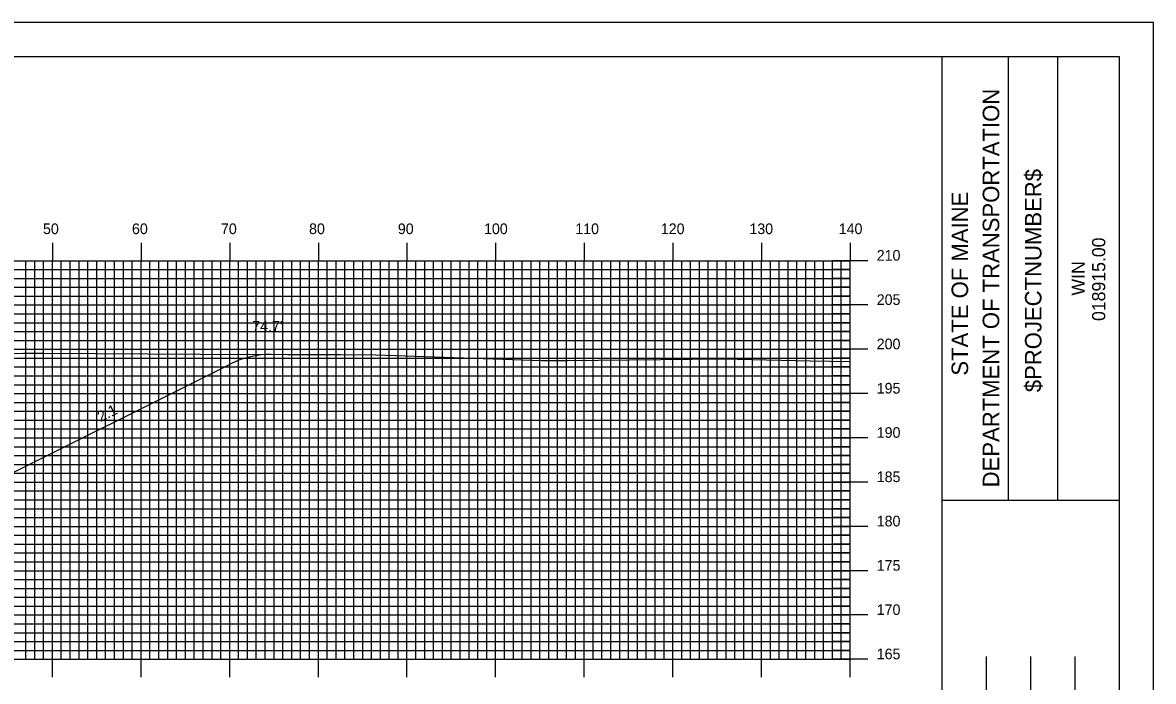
# Model space of a CAD drawing. Extents: x 1796027 to 1796370, y 442591 to 442811.
# Drawn here: x 1796239 to 1796366.6, y 442736.2 to 442810.5 of the extents above; entities that cross this region are included whole.
import ezdxf

# ---------------------------------------------------------------- set-up
doc = ezdxf.new("R2010")
doc.units = 0
for name, color, linetype in [('ANNOTATION', 7, 'Continuous'), ('BORDER', 7, 'Continuous'), ('D_Roadway_SlopeLines', 7, 'Continuous'), ('D_Text_Standard', 7, 'Continuous'), ('H_V ANNOTATION', 7, 'Continuous'), ('MAJOR', 7, 'Continuous'), ('MINOR', 7, 'Continuous'), ('PLOT BOUNDARY', 7, 'Continuous'), ('S_Roadway_Centerline', 7, 'Continuous')]:
    doc.layers.add(name, color=color, linetype=linetype)

msp = doc.modelspace()

# ---------------------------------------------------------------- linework, layer by layer
at = {"layer": 'ANNOTATION'}
msp.add_arc((1796267, 442763.09), 10, 89.662, 116.5651, dxfattribs=at)
msp.add_arc((1796267, 442763.09), 10, 89.662, 116.5651, dxfattribs=at)
at = {"layer": 'BORDER'}
for p, q in [((1796342.79, 442596.67), (1796342.79, 442806.67)), ((1796350.25, 442756.66), (1796350.25, 442806.66)), ((1796355.84, 442756.66), (1796355.84, 442806.66)), ((1796342.79, 442756.65), (1796362.79, 442756.65)), ((1796347.79, 442721.67), (1796347.79, 442738.97)), ((1796352.79, 442721.67), (1796352.79, 442738.97)), ((1796357.79, 442721.67), (1796357.79, 442738.97))]:
    msp.add_line(p, q, dxfattribs=at)
msp.add_lwpolyline([(1796042.79, 442596.67), (1796362.79, 442596.67), (1796362.79, 442806.67), (1796042.79, 442806.67)], close=True, dxfattribs=at)
at = {"layer": 'D_Roadway_SlopeLines'}
msp.add_lwpolyline([(1796228.99, 442758.27), (1796234.99, 442758.27), (1796262.53, 442772.04)], dxfattribs=at)
at = {"layer": 'MAJOR'}
for p, q in [((1796242.39, 442785.67), (1796242.39, 442783.67)), ((1796252.39, 442785.67), (1796252.39, 442783.67)), ((1796262.39, 442785.67), (1796262.39, 442783.67)), ((1796272.39, 442785.67), (1796272.39, 442783.67)), ((1796282.39, 442785.67), (1796282.39, 442783.67)), ((1796292.39, 442785.67), (1796292.39, 442783.67)), ((1796302.39, 442785.67), (1796302.39, 442783.67)), ((1796312.39, 442785.67), (1796312.39, 442783.67)), ((1796322.39, 442785.67), (1796322.39, 442783.67)), ((1796332.39, 442785.67), (1796332.39, 442783.67)), ((1796052.39, 442783.67), (1796332.39, 442783.67)), ((1796052.39, 442783.67), (1796332.39, 442783.67)), ((1796242.39, 442738.67), (1796242.39, 442783.67)), ((1796252.39, 442738.67), (1796252.39, 442783.67)), ((1796262.39, 442738.67), (1796262.39, 442783.67)), ((1796272.39, 442738.67), (1796272.39, 442783.67)), ((1796282.39, 442738.67), (1796282.39, 442783.67)), ((1796292.39, 442738.67), (1796292.39, 442783.67)), ((1796302.39, 442738.67), (1796302.39, 442783.67)), ((1796312.39, 442738.67), (1796312.39, 442783.67)), ((1796322.39, 442738.67), (1796322.39, 442783.67)), ((1796334.4, 442783.67), (1796330.39, 442783.67)), ((1796332.39, 442738.67), (1796332.39, 442783.67)), ((1796332.39, 442738.67), (1796332.39, 442783.67)), ((1796052.39, 442778.67), (1796332.39, 442778.67)), ((1796334.4, 442778.67), (1796330.39, 442778.67)), ((1796052.39, 442773.67), (1796332.39, 442773.67)), ((1796334.4, 442773.67), (1796330.39, 442773.67)), ((1796052.39, 442768.67), (1796332.39, 442768.67)), ((1796334.4, 442768.67), (1796330.39, 442768.67)), ((1796052.39, 442763.67), (1796332.39, 442763.67)), ((1796334.4, 442763.67), (1796330.39, 442763.67)), ((1796052.39, 442758.67), (1796332.39, 442758.67)), ((1796334.4, 442758.67), (1796330.39, 442758.67)), ((1796052.39, 442753.67), (1796332.39, 442753.67)), ((1796334.4, 442753.67), (1796330.39, 442753.67)), ((1796052.39, 442748.67), (1796332.39, 442748.67)), ((1796334.4, 442748.67), (1796330.39, 442748.67)), ((1796052.39, 442743.67), (1796332.39, 442743.67)), ((1796334.4, 442743.67), (1796330.39, 442743.67)), ((1796052.39, 442738.67), (1796332.39, 442738.67)), ((1796052.39, 442738.67), (1796332.39, 442738.67)), ((1796242.39, 442736.66), (1796242.39, 442738.67)), ((1796252.39, 442736.66), (1796252.39, 442738.67)), ((1796262.39, 442736.66), (1796262.39, 442738.67)), ((1796272.39, 442736.66), (1796272.39, 442738.67)), ((1796282.39, 442736.66), (1796282.39, 442738.67)), ((1796292.39, 442736.66), (1796292.39, 442738.67)), ((1796302.39, 442736.66), (1796302.39, 442738.67)), ((1796312.39, 442736.66), (1796312.39, 442738.67)), ((1796322.39, 442736.66), (1796322.39, 442738.67)), ((1796334.4, 442738.67), (1796330.39, 442738.67)), ((1796332.39, 442736.66), (1796332.39, 442738.67))]:
    msp.add_line(p, q, dxfattribs=at)
at = {"layer": 'MINOR'}
for p, q in [((1796239.39, 442738.67), (1796239.39, 442783.67)), ((1796240.39, 442738.67), (1796240.39, 442783.67)), ((1796241.39, 442738.67), (1796241.39, 442783.67)), ((1796243.39, 442738.67), (1796243.39, 442783.67)), ((1796244.39, 442738.67), (1796244.39, 442783.67)), ((1796245.39, 442738.67), (1796245.39, 442783.67)), ((1796246.39, 442738.67), (1796246.39, 442783.67)), ((1796247.39, 442738.67), (1796247.39, 442783.67)), ((1796248.39, 442738.67), (1796248.39, 442783.67)), ((1796249.39, 442738.67), (1796249.39, 442783.67)), ((1796250.39, 442738.67), (1796250.39, 442783.67)), ((1796251.39, 442738.67), (1796251.39, 442783.67)), ((1796253.39, 442738.67), (1796253.39, 442783.67)), ((1796254.39, 442738.67), (1796254.39, 442783.67)), ((1796255.39, 442738.67), (1796255.39, 442783.67)), ((1796256.39, 442738.67), (1796256.39, 442783.67)), ((1796257.39, 442738.67), (1796257.39, 442783.67)), ((1796258.39, 442738.67), (1796258.39, 442783.67)), ((1796259.39, 442738.67), (1796259.39, 442783.67)), ((1796260.39, 442738.67), (1796260.39, 442783.67)), ((1796261.39, 442738.67), (1796261.39, 442783.67)), ((1796263.39, 442738.67), (1796263.39, 442783.67)), ((1796264.39, 442738.67), (1796264.39, 442783.67)), ((1796265.39, 442738.67), (1796265.39, 442783.67)), ((1796266.39, 442738.67), (1796266.39, 442783.67)), ((1796267.39, 442738.67), (1796267.39, 442783.67)), ((1796268.39, 442738.67), (1796268.39, 442783.67)), ((1796269.39, 442738.67), (1796269.39, 442783.67)), ((1796270.39, 442738.67), (1796270.39, 442783.67)), ((1796271.39, 442738.67), (1796271.39, 442783.67)), ((1796273.39, 442738.67), (1796273.39, 442783.67)), ((1796274.39, 442738.67), (1796274.39, 442783.67)), ((1796275.39, 442738.67), (1796275.39, 442783.67)), ((1796276.39, 442738.67), (1796276.39, 442783.67)), ((1796277.39, 442738.67), (1796277.39, 442783.67)), ((1796278.39, 442738.67), (1796278.39, 442783.67)), ((1796279.39, 442738.67), (1796279.39, 442783.67)), ((1796280.39, 442738.67), (1796280.39, 442783.67)), ((1796281.39, 442738.67), (1796281.39, 442783.67)), ((1796283.39, 442738.67), (1796283.39, 442783.67)), ((1796284.39, 442738.67), (1796284.39, 442783.67)), ((1796285.39, 442738.67), (1796285.39, 442783.67)), ((1796286.39, 442738.67), (1796286.39, 442783.67)), ((1796287.39, 442738.67), (1796287.39, 442783.67)), ((1796288.39, 442738.67), (1796288.39, 442783.67)), ((1796289.39, 442738.67), (1796289.39, 442783.67)), ((1796290.39, 442738.67), (1796290.39, 442783.67)), ((1796291.39, 442738.67), (1796291.39, 442783.67)), ((1796293.39, 442738.67), (1796293.39, 442783.67)), ((1796294.39, 442738.67), (1796294.39, 442783.67)), ((1796295.39, 442738.67), (1796295.39, 442783.67)), ((1796296.39, 442738.67), (1796296.39, 442783.67)), ((1796297.39, 442738.67), (1796297.39, 442783.67)), ((1796298.39, 442738.67), (1796298.39, 442783.67)), ((1796299.39, 442738.67), (1796299.39, 442783.67)), ((1796300.39, 442738.67), (1796300.39, 442783.67)), ((1796301.39, 442738.67), (1796301.39, 442783.67)), ((1796303.39, 442738.67), (1796303.39, 442783.67)), ((1796304.39, 442738.67), (1796304.39, 442783.67)), ((1796305.39, 442738.67), (1796305.39, 442783.67)), ((1796306.39, 442738.67), (1796306.39, 442783.67)), ((1796307.39, 442738.67), (1796307.39, 442783.67)), ((1796308.39, 442738.67), (1796308.39, 442783.67)), ((1796309.39, 442738.67), (1796309.39, 442783.67)), ((1796310.39, 442738.67), (1796310.39, 442783.67)), ((1796311.39, 442738.67), (1796311.39, 442783.67)), ((1796313.39, 442738.67), (1796313.39, 442783.67)), ((1796314.39, 442738.67), (1796314.39, 442783.67)), ((1796315.39, 442738.67), (1796315.39, 442783.67)), ((1796316.39, 442738.67), (1796316.39, 442783.67)), ((1796317.39, 442738.67), (1796317.39, 442783.67)), ((1796318.39, 442738.67), (1796318.39, 442783.67)), ((1796319.39, 442738.67), (1796319.39, 442783.67)), ((1796320.39, 442738.67), (1796320.39, 442783.67)), ((1796321.39, 442738.67), (1796321.39, 442783.67)), ((1796323.39, 442738.67), (1796323.39, 442783.67)), ((1796324.39, 442738.67), (1796324.39, 442783.67)), ((1796325.39, 442738.67), (1796325.39, 442783.67)), ((1796326.39, 442738.67), (1796326.39, 442783.67)), ((1796327.39, 442738.67), (1796327.39, 442783.67)), ((1796328.39, 442738.67), (1796328.39, 442783.67)), ((1796329.39, 442738.67), (1796329.39, 442783.67)), ((1796330.39, 442738.67), (1796330.39, 442783.67)), ((1796331.39, 442738.67), (1796331.39, 442783.67)), ((1796052.39, 442782.67), (1796332.39, 442782.67)), ((1796332.39, 442782.67), (1796330.39, 442782.67)), ((1796052.39, 442781.67), (1796332.39, 442781.67)), ((1796332.39, 442781.67), (1796330.39, 442781.67)), ((1796052.39, 442780.67), (1796332.39, 442780.67)), ((1796052.39, 442779.67), (1796332.39, 442779.67)), ((1796332.39, 442780.67), (1796330.39, 442780.67)), ((1796332.39, 442779.67), (1796330.39, 442779.67)), ((1796052.39, 442777.67), (1796332.39, 442777.67)), ((1796332.39, 442777.67), (1796330.39, 442777.67)), ((1796052.39, 442776.67), (1796332.39, 442776.67)), ((1796052.39, 442775.67), (1796332.39, 442775.67)), ((1796332.39, 442776.67), (1796330.39, 442776.67)), ((1796332.39, 442775.67), (1796330.39, 442775.67)), ((1796052.39, 442774.67), (1796332.39, 442774.67)), ((1796332.39, 442774.67), (1796330.39, 442774.67)), ((1796052.39, 442772.67), (1796332.39, 442772.67)), ((1796332.39, 442772.67), (1796330.39, 442772.67)), ((1796052.39, 442771.67), (1796332.39, 442771.67)), ((1796052.39, 442770.67), (1796332.39, 442770.67)), ((1796332.39, 442771.67), (1796330.39, 442771.67)), ((1796332.39, 442770.67), (1796330.39, 442770.67)), ((1796052.39, 442769.67), (1796332.39, 442769.67)), ((1796332.39, 442769.67), (1796330.39, 442769.67)), ((1796052.39, 442767.67), (1796332.39, 442767.67)), ((1796052.39, 442766.67), (1796332.39, 442766.67)), ((1796332.39, 442767.67), (1796330.39, 442767.67)), ((1796332.39, 442766.67), (1796330.39, 442766.67)), ((1796052.39, 442765.67), (1796332.39, 442765.67)), ((1796332.39, 442765.67), (1796330.39, 442765.67)), ((1796052.39, 442764.67), (1796332.39, 442764.67)), ((1796332.39, 442764.67), (1796330.39, 442764.67)), ((1796052.39, 442762.67), (1796332.39, 442762.67)), ((1796052.39, 442761.67), (1796332.39, 442761.67)), ((1796332.39, 442762.67), (1796330.39, 442762.67)), ((1796332.39, 442761.67), (1796330.39, 442761.67)), ((1796052.39, 442760.67), (1796332.39, 442760.67)), ((1796332.39, 442760.67), (1796330.39, 442760.67)), ((1796052.39, 442759.67), (1796332.39, 442759.67)), ((1796332.39, 442759.67), (1796330.39, 442759.67)), ((1796052.39, 442757.67), (1796332.39, 442757.67)), ((1796052.39, 442756.67), (1796332.39, 442756.67)), ((1796332.39, 442757.67), (1796330.39, 442757.67)), ((1796332.39, 442756.67), (1796330.39, 442756.67)), ((1796052.39, 442755.67), (1796332.39, 442755.67)), ((1796332.39, 442755.67), (1796330.39, 442755.67)), ((1796052.39, 442754.67), (1796332.39, 442754.67)), ((1796332.39, 442754.67), (1796330.39, 442754.67)), ((1796052.39, 442752.67), (1796332.39, 442752.67)), ((1796332.39, 442752.67), (1796330.39, 442752.67)), ((1796052.39, 442751.67), (1796332.39, 442751.67)), ((1796332.39, 442751.67), (1796330.39, 442751.67)), ((1796052.39, 442750.67), (1796332.39, 442750.67)), ((1796332.39, 442750.67), (1796330.39, 442750.67)), ((1796052.39, 442749.67), (1796332.39, 442749.67)), ((1796332.39, 442749.67), (1796330.39, 442749.67)), ((1796052.39, 442747.67), (1796332.39, 442747.67)), ((1796332.39, 442747.67), (1796330.39, 442747.67)), ((1796052.39, 442746.67), (1796332.39, 442746.67)), ((1796332.39, 442746.67), (1796330.39, 442746.67)), ((1796052.39, 442745.67), (1796332.39, 442745.67)), ((1796332.39, 442745.67), (1796330.39, 442745.67)), ((1796052.39, 442744.67), (1796332.39, 442744.67)), ((1796332.39, 442744.67), (1796330.39, 442744.67)), ((1796052.39, 442742.67), (1796332.39, 442742.67)), ((1796332.39, 442742.67), (1796330.39, 442742.67)), ((1796052.39, 442741.67), (1796332.39, 442741.67)), ((1796332.39, 442741.67), (1796330.39, 442741.67)), ((1796052.39, 442740.67), (1796332.39, 442740.67)), ((1796332.39, 442740.67), (1796330.39, 442740.67)), ((1796052.39, 442739.67), (1796332.39, 442739.67)), ((1796332.39, 442739.67), (1796330.39, 442739.67))]:
    msp.add_line(p, q, dxfattribs=at)
at = {"layer": 'PLOT BOUNDARY'}
msp.add_lwpolyline([(1796026.61, 442590.55), (1796366.61, 442590.55), (1796366.61, 442810.55), (1796026.61, 442810.55)], close=True, dxfattribs=at)
at = {"layer": 'S_Roadway_Centerline'}
msp.add_lwpolyline([(1796227.64, 442773.15), (1796239.14, 442773.23), (1796239.93, 442773.24), (1796241.31, 442773.22), (1796259.09, 442773.12), (1796268.94, 442773.08), (1796274.89, 442773.09), (1796278.89, 442773.05), (1796297.59, 442772.39), (1796298.61, 442772.39), (1796300.49, 442772.39), (1796318.04, 442772.58), (1796327.89, 442772.37), (1796332.39, 442772.27)], dxfattribs=at)

# ---------------------------------------------------------------- texts
at = {"layer": 'ANNOTATION'}
msp.add_text('2:1', height=1.2, rotation=26.5651, dxfattribs=at).set_placement((1796247.83, 442765.44))
msp.add_text('2:1', height=1.2, rotation=26.5651, dxfattribs=at).set_placement((1796247.83, 442765.44))
at = {"layer": 'BORDER'}
for s, height, p in [('DEPARTMENT OF TRANSPORTATION', 1.8635, (1796349.21, 442758.08)), ('$PROJECTNUMBER$', 1.8635, (1796353.98, 442768.82)), ('STATE OF MAINE', 1.8635, (1796345.7, 442770.69)), ('018915.00', 1.491, (1796361.18, 442776.86)), ('WIN', 1.491, (1796358.87, 442779.73))]:
    msp.add_text(s, height=height, rotation=90, dxfattribs=at).set_placement(p)
at = {"layer": 'D_Text_Standard'}
msp.add_text("74.7'", height=1.2, dxfattribs=at).set_placement((1796264.93, 442775.67))
at = {"layer": 'H_V ANNOTATION'}
for s, p in [('50', (1796241.32, 442786.67)), ('60', (1796251.36, 442786.67)), ('70', (1796261.4, 442786.67)), ('80', (1796271.34, 442786.67)), ('90', (1796281.36, 442786.67)), ('100', (1796291.08, 442786.67)), ('110', (1796301.38, 442786.67)), ('120', (1796311.03, 442786.67)), ('130', (1796321.02, 442786.67)), ('140', (1796331.1, 442786.67)), ('210', (1796335.39, 442783.67)), ('205', (1796335.39, 442778.67)), ('200', (1796335.39, 442773.67)), ('195', (1796335.39, 442768.67)), ('190', (1796335.39, 442763.67)), ('185', (1796335.39, 442758.67)), ('180', (1796335.39, 442753.67)), ('175', (1796335.39, 442748.67)), ('170', (1796335.39, 442743.67)), ('165', (1796335.39, 442738.67))]:
    msp.add_text(s, height=1.2, dxfattribs=at).set_placement(p)

doc.saveas('drawing.dxf')
